(* Logix 5000 project; controller MNETR_V13 1756-L63 rev 13.1; software revision 13.03 *)

TASK MainTask (continuous, watchdog 500 ms) : MainProgram

MODULES
   Local : 1756-L63 (ICP 0, rev 13.1)
      LocalENBT : 1756-ENBT (ICP 3, Ethernet 105.102.0.224, rev 2.4)
         RemoteENBT : 1756-ENBT (Ethernet 105.102.0.210, rev 1.6, Output RPI 10 ms)
            MNETR : vendor 1 type 0 code 15 (ICP 1, rev 1.1, Output RPI 5 ms)
END_MODULES

TYPE MNETRBLOCKSTATS :
STRUCT
   Read : INT;   // Total number of read block transfers
   Write : INT;   // Total number of write block transfers
   Parse : INT;   // Total number of blocks parsed
   Event : INT;   // Total number of event blocks received
   Cmd : INT;   // Total number of command blocks received
   Err : INT;   // Total number of block transfer errors
END_STRUCT
END_TYPE

TYPE MNETRCLIENTSTATS :
STRUCT
   CmdReq : INT;   // Total number of command list requests sent
   CmdResp : INT;   // Total number of command list responses received
   CmdErr : INT;   // Total number of command list errors
   Requests : INT;   // Total number of requests for port
   Responses : INT;   // Total number of responses for port
   ErrSent : INT;   // Total number of errors sent
   ErrRec : INT;   // Total number of errors received
   CfgErrWord : INT;   // Configuration Error Word
   CurErr : INT;   // Current Error code
   LastErr : INT;   // Last recorded error code
END_STRUCT
END_TYPE

TYPE MNETRCMDCONTROL :
STRUCT
   CmdIndex : INT[6];   // Stores the command indexes for command control.
   NumberOfCommands : INT;   // Number of commands per block (1 to 6)
   CommandsAddedtoQueue : INT;   // Number of commands added to queue
   CmdControlTrigger : BOOL;   // Trigger Command Control. User application will activate this trigger.
END_STRUCT
END_TYPE

TYPE MNETRCOILARRAY :   // Conversion to INT values
STRUCT
   Boolean : BOOL[416];   // Conversion from Bool to INT data types
END_STRUCT
END_TYPE

TYPE MNETRCONTROL :   // Module Behaviour Control Tags. Values used by program for data transfer operation between the module and the processor.
STRUCT
   BootTimer : TIMER;   // Starts counting when user issues a coldboot or warmboot
   WarmBoot : BOOL;   // Causes software reset. The Module reads new configuration information.
   ColdBoot : BOOL;   // Causes hardware reset.
   EventCmdTrigger : BOOL;   // Trigger events to be executed by the module
   EventCmd : MNETREVENTCMD;   // Event command Data
   CmdControl : MNETRCMDCONTROL;   // Command control data
   PassThru : MNETRPASSTHRU;   // Pass thru data format
   IPAddress : MNETRIPADDRESS;   // Getting and Setting IP address to and from Module
END_STRUCT
END_TYPE

TYPE MNETRDATA :
STRUCT
   ReadData : INT[600];   // Data read from module
   WriteData : INT[600];   // Data to write to module
END_STRUCT
END_TYPE

TYPE MNETREVENTCMD :   // Data structure to use for Event message generation.
STRUCT
   IP0 : INT;   // First digit of IP address
   IP1 : INT;   // Second digit of IP address
   IP2 : INT;   // Third digit of IP address
   IP3 : INT;   // Last digit of IP address
   ServPort : INT;   // TCP Service Port number (0-65535), 502 for MBAP, 2000 for MNET
   Node : INT;   // Modbus slave node address (0 to 247)
   DBAddress : INT;   // Module internal database to use with message
   Count : INT;   // Register or data point count
   Swap : INT;   // Swap code to use with functions 3 and 4
   Function : INT;   // Modbus function code for message
   Address : INT;   // Address to interface with in device
   Result : INT;   // shows the result of the event that was sent
END_STRUCT
END_TYPE

TYPE MNETRIPADDRESS :   // Data structure to get and set the IP address of the module.
STRUCT
   IPGetTrigger : BOOL;   // Gets IP address.
   IPReceived : INT[4];   // IP address received.
   IPSetTrigger : BOOL;   // Sets IP address
   IPRequested : INT[4];   // IP address set.
END_STRUCT
END_TYPE

TYPE MNETRMODULEDEF :   // this defines the whole module which includes all tags used in the program
STRUCT
   DATA : MNETRDATA;   // Data read from module
   STATUS : MNETRSTATUS;   // Client ,Server Status and blocks status
   CONTROL : MNETRCONTROL;   // Module control warmboot, coldboot, etc
   UTIL : MNETRUTIL;   // command, event control
END_STRUCT
END_TYPE

TYPE MNETRPASSTHRU :   // Applicable with the selection of a Pass-Through mode (1 to 3) in the Configuration file.
STRUCT
   MBControl1 : CONTROL;   // Modbus pass thru message control
   MBControl2 : CONTROL;   // Modbus pass thru message control
   MBMsg : SINT[500];   // message array
   MBScratch : INT[3];   // temporary used ints
   MBOffsetBit : INT;   // offset bit in the message
   MBOffset : INT;   // start offset in the message
   MBMsgLen : INT;   // message length
   mbdouble : DINT;   // Modbus double int tag
   MBCoil : MNETRCOILARRAY;   // Conversion array
END_STRUCT
END_TYPE

TYPE MNETRSTATUS :
STRUCT
   PassCnt : INT;   // Program cycle counter
   ProductVersion : INT;   // Shows the module software version
   ProductCode : INT[2];   // This identifies the module product code
   BlockStats : MNETRBLOCKSTATS;   // Block Transfer Statistics.
   Reserved1 : INT;   // Reserved INT
   Reserved2 : INT;   // Reserved INT
   MNetReq : INT;   // number of remote client requests for port 502
   MNetResp : INT;   // number of server responses for port 502
   MBAPReq : INT;   // number of remote client requests for port 2000
   MBAPResp : INT;   // number of server responses for port 2000
   ClientStatus : MNETRCLIENTSTATS;   // Client Status
END_STRUCT
END_TYPE

TYPE MNETRUTIL :   // Variables for internal ladder usage - should not be accessed by user application
STRUCT
   LastRead : INT;   // Index of last read block
   LastWrite : INT;   // Index of last write block
   BlockIndex : INT;   // Computed block offset for data table
   ReadDataSizeGet : INT;   // Gets ReadData Array Length.
   WriteDataSizeGet : INT;   // Gets WriteData Array Length.
   ReadDataBlkCount : INT;   // Holds the value of the Block Counts of the Read Data Array. Array Size is divided by 40.
   WriteDataBlkCount : INT;   // Holds the value of the Block Counts of the Write Data Array. Array Size is divided by 40.
   RBTSremainder : INT;   // Holds remainder calculation value from the read array.
   WBTSremainder : INT;   // Holds remainder calculation value from the write array.
   IPsetPending : BOOL;   // Allows Setting module IP address
   IPgetPending : BOOL;   // Allows Getting module IP address
   InitOutBlkIDLim : INT;   // Block Index Limit for ReadData size of the array
END_STRUCT
END_TYPE

VAR_GLOBAL   (* controller tags *)
   MJFAULTS : DINT[12] := ([0] := 1272054862, [1] := 191551, [3] := 1256603824, [4] := 191551);
   MNETR : MNETRMODULEDEF;
END_VAR

PROGRAM MainProgram   (* routine attr 65 MainRoutine *)

ROUTINE MainRoutine   (* ladder *)
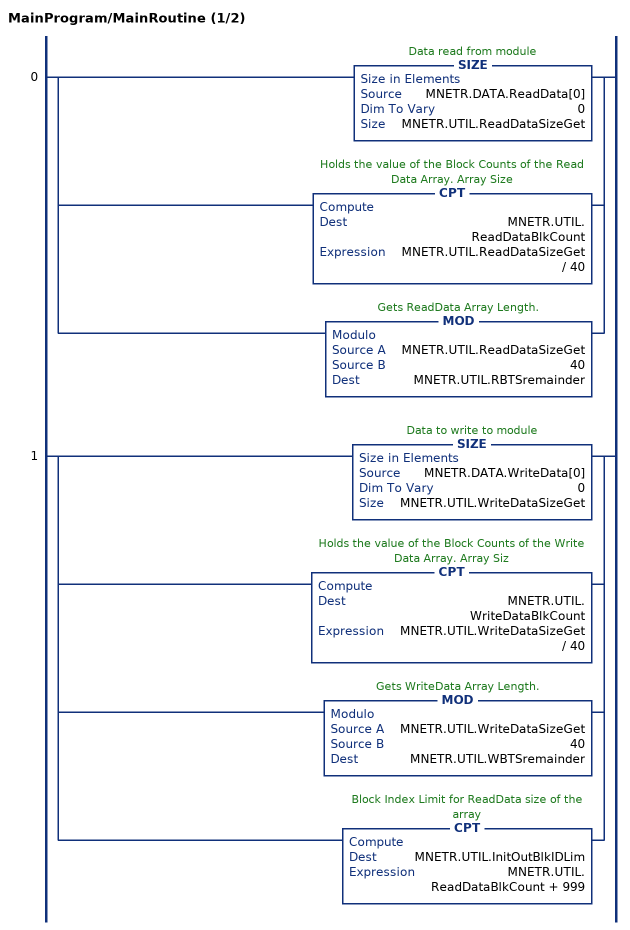
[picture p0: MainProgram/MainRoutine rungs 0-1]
   0: [SIZE(MNETR.DATA.ReadData[0],0,MNETR.UTIL.ReadDataSizeGet) ,CPT(MNETR.UTIL.ReadDataBlkCount,MNETR.UTIL.ReadDataSizeGet / 40) ,MOD(MNETR.UTIL.ReadDataSizeGet,40,MNETR.UTIL.RBTSremainder) ];
   1: [SIZE(MNETR.DATA.WriteData[0],0,MNETR.UTIL.WriteDataSizeGet) ,CPT(MNETR.UTIL.WriteDataBlkCount,MNETR.UTIL.WriteDataSizeGet / 40) ,MOD(MNETR.UTIL.WriteDataSizeGet,40,MNETR.UTIL.WBTSremainder) ,CPT(MNETR.UTIL.InitOutBlkIDLim,MNETR.UTIL.ReadDataBlkCount + 999) ];
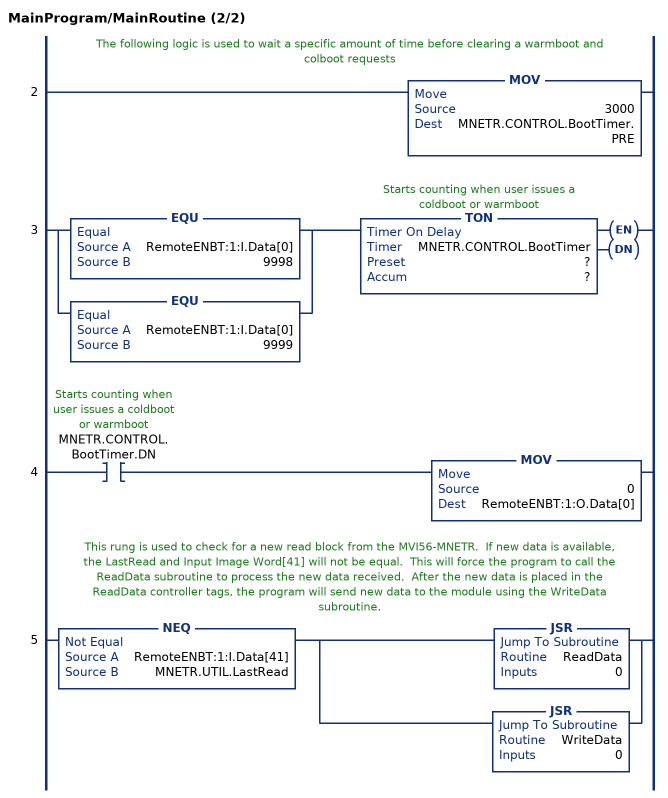
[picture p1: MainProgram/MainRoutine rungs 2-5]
   // The following logic is used to wait a specific amount of time before clearing a warmboot and colboot requests
   2: MOV(3000,MNETR.CONTROL.BootTimer.PRE);
   3: [EQU(RemoteENBT:1:I.Data[0],9998) ,EQU(RemoteENBT:1:I.Data[0],9999) ]TON(MNETR.CONTROL.BootTimer,?,?);
   4: XIC(MNETR.CONTROL.BootTimer.DN)MOV(0,RemoteENBT:1:O.Data[0]);
   // This rung is used to check for a new read block from the MVI56-MNETR.  If new data is available, the LastRead and Input Image Word[41] will not be equal.  This will force the program to call the ReadData subroutine to process the new data received.  After the new data is placed in the ReadData controller tags, the program will send new data to the module using the WriteData subroutine.
   5: NEQ(RemoteENBT:1:I.Data[41],MNETR.UTIL.LastRead)[JSR(ReadData,0) ,JSR(WriteData,0) ];
END_ROUTINE

ROUTINE ReadData   (* ladder *)
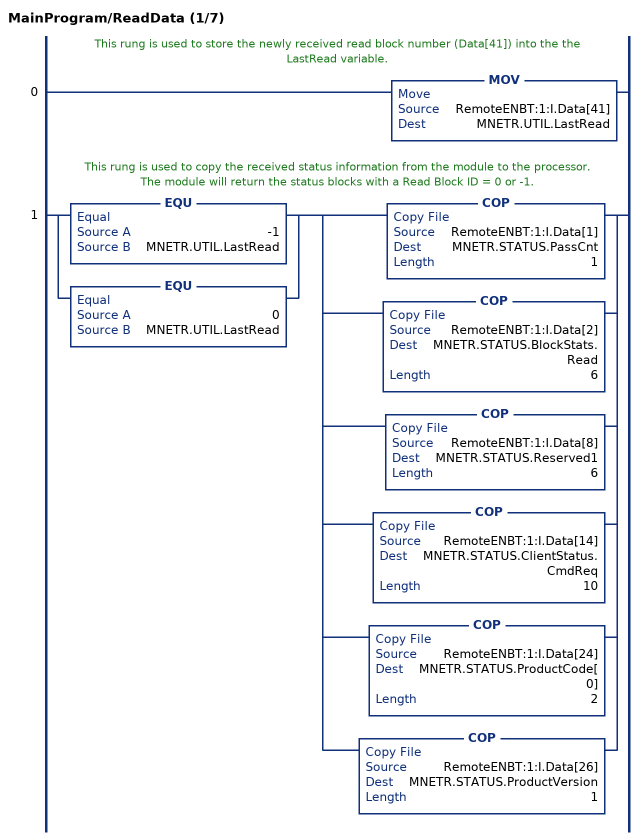
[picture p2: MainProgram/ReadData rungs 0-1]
   // This rung is used to store the newly received read block number (Data[41]) into the the LastRead variable.
   0: MOV(RemoteENBT:1:I.Data[41],MNETR.UTIL.LastRead);
   // This rung is used to copy the received status information from the module to the processor. The module will return the status blocks with a Read Block ID = 0 or -1.
   1: [EQU(-1,MNETR.UTIL.LastRead) ,EQU(0,MNETR.UTIL.LastRead) ][COP(RemoteENBT:1:I.Data[1],MNETR.STATUS.PassCnt,1) ,COP(RemoteENBT:1:I.Data[2],MNETR.STATUS.BlockStats.Read,6) ,COP(RemoteENBT:1:I.Data[8],MNETR.STATUS.Reserved1,6) ,COP(RemoteENBT:1:I.Data[14],MNETR.STATUS.ClientStatus.CmdReq,10) ,COP(RemoteENBT:1:I.Data[24],MNETR.STATUS.ProductCode[0],2) ,COP(RemoteENBT:1:I.Data[26],MNETR.STATUS.ProductVersion,1) ];
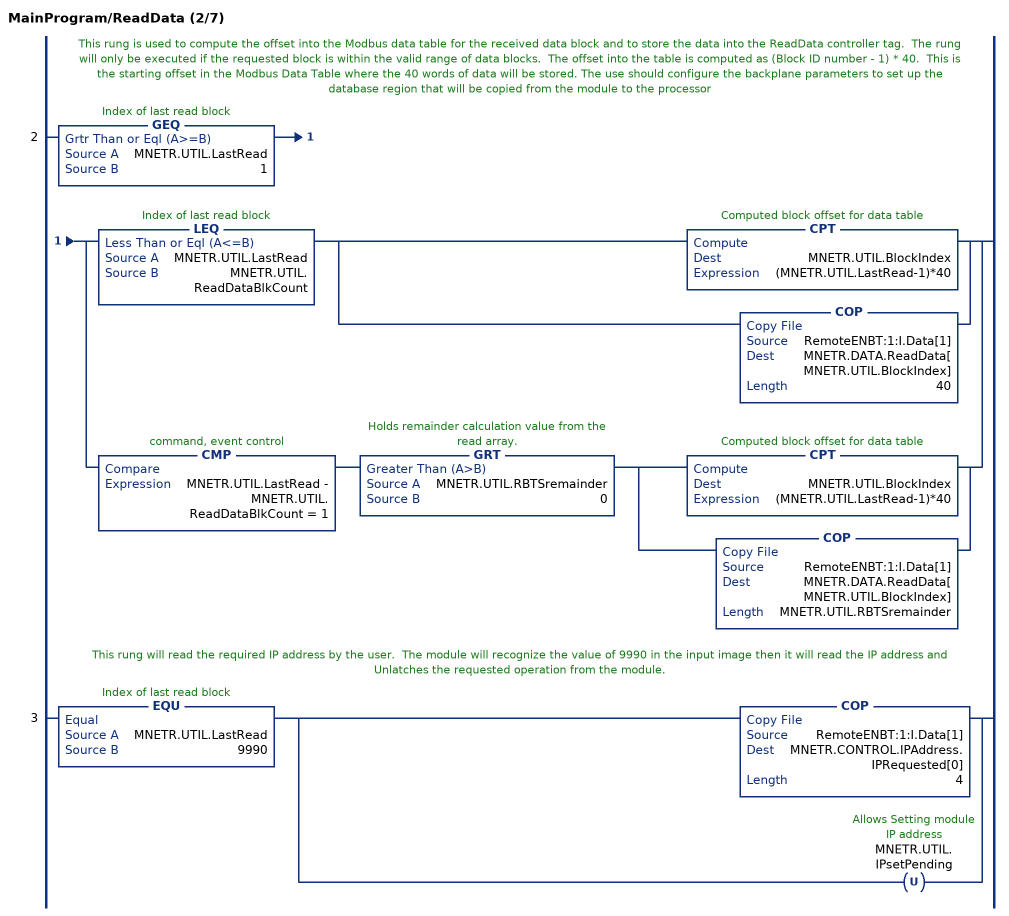
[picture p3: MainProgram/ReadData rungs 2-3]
   // This rung is used to compute the offset into the Modbus data table for the received data block and to store the data into the ReadData controller tag.  The rung will only be executed if the requested block is within the valid range of data blocks.  The offset into the table is computed as (Block ID number - 1) * 40.  This is the starting offset in the Modbus Data Table where the 40 words of data will be stored. The use should configure the backplane parameters to set up the database region that will be copied from the module to the processor
   2: GEQ(MNETR.UTIL.LastRead,1)[LEQ(MNETR.UTIL.LastRead,MNETR.UTIL.ReadDataBlkCount) [CPT(MNETR.UTIL.BlockIndex,(MNETR.UTIL.LastRead-1)*40) ,COP(RemoteENBT:1:I.Data[1],MNETR.DATA.ReadData[MNETR.UTIL.BlockIndex],40) ] ,CMP(MNETR.UTIL.LastRead - MNETR.UTIL.ReadDataBlkCount = 1) GRT(MNETR.UTIL.RBTSremainder,0) [CPT(MNETR.UTIL.BlockIndex,(MNETR.UTIL.LastRead-1)*40) ,COP(RemoteENBT:1:I.Data[1],MNETR.DATA.ReadData[MNETR.UTIL.BlockIndex],MNETR.UTIL.RBTSremainder) ] ];
   // This rung will read the required IP address by the user.  The module will recognize the value of 9990 in the input image then it will read the IP address and Unlatches the requested operation from the module.
   3: EQU(MNETR.UTIL.LastRead,9990)[COP(RemoteENBT:1:I.Data[1],MNETR.CONTROL.IPAddress.IPRequested[0],4) ,OTU(MNETR.UTIL.IPsetPending) ];
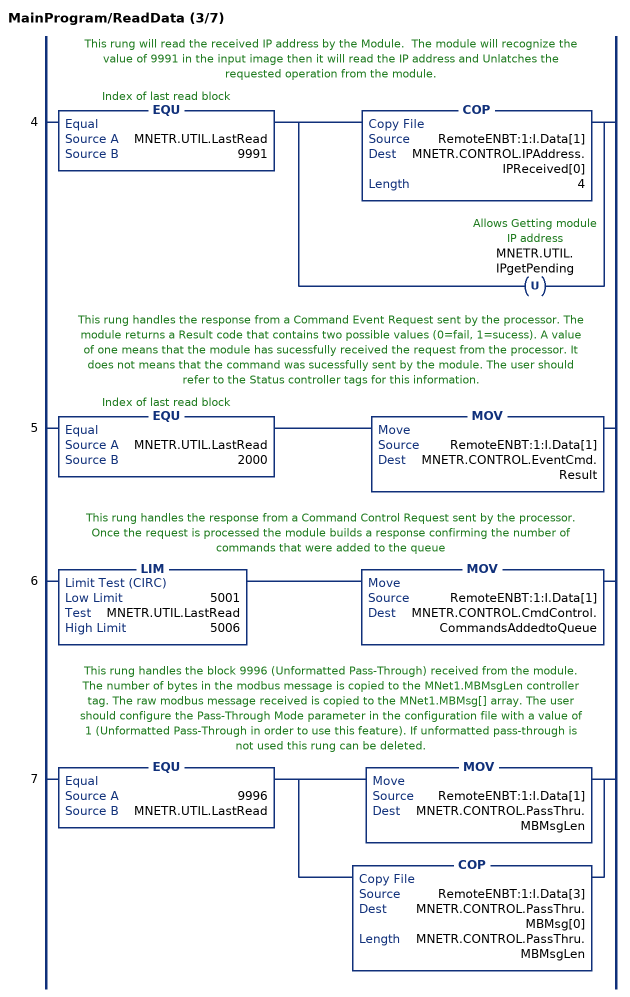
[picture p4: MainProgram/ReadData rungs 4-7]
   // This rung will read the received IP address by the Module.  The module will recognize the value of 9991 in the input image then it will read the IP address and Unlatches the requested operation from the module.
   4: EQU(MNETR.UTIL.LastRead,9991)[COP(RemoteENBT:1:I.Data[1],MNETR.CONTROL.IPAddress.IPReceived[0],4) ,OTU(MNETR.UTIL.IPgetPending) ];
   // This rung handles the response from a Command Event Request sent by the processor. The module returns a Result code that contains two possible values (0=fail, 1=sucess). A value of one means that the module has sucessfully received the request from the processor. It does not means that the command was sucessfully sent by the module. The user should refer to the Status controller tags for this information.
   5: EQU(MNETR.UTIL.LastRead,2000)MOV(RemoteENBT:1:I.Data[1],MNETR.CONTROL.EventCmd.Result);
   // This rung handles the response from a Command Control Request sent by the processor. Once the request is processed the module builds a response confirming the number of commands that were added to the queue
   6: LIM(5001,MNETR.UTIL.LastRead,5006)MOV(RemoteENBT:1:I.Data[1],MNETR.CONTROL.CmdControl.CommandsAddedtoQueue);
   // This rung handles the block 9996 (Unformatted Pass-Through) received from the module. The number of bytes in the modbus message is copied to the MNet1.MBMsgLen controller tag. The raw modbus message received is copied to the MNet1.MBMsg[] array. The user should configure the Pass-Through Mode parameter in the configuration file with a value of 1 (Unformatted Pass-Through in order to use this feature). If unformatted pass-through is not used this rung can be deleted.
   7: EQU(9996,MNETR.UTIL.LastRead)[MOV(RemoteENBT:1:I.Data[1],MNETR.CONTROL.PassThru.MBMsgLen) ,COP(RemoteENBT:1:I.Data[3],MNETR.CONTROL.PassThru.MBMsg[0],MNETR.CONTROL.PassThru.MBMsgLen) ];
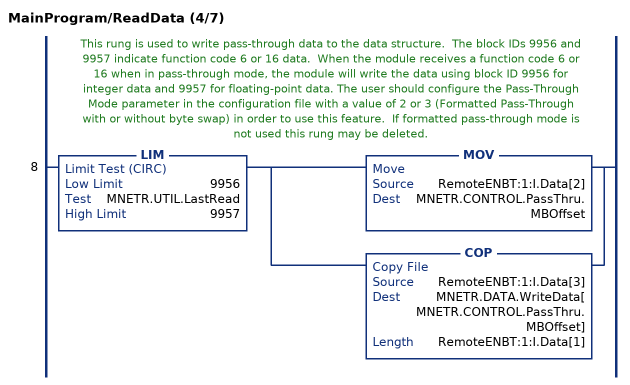
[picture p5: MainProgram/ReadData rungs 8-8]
   // This rung is used to write pass-through data to the data structure.  The block IDs 9956 and 9957 indicate function code 6 or 16 data.  When the module receives a function code 6 or 16 when in pass-through mode, the module will write the data using block ID 9956 for integer data and 9957 for floating-point data. The user should configure the Pass-Through Mode parameter in the configuration file with a value of 2 or 3 (Formatted Pass-Through with or without byte swap) in order to use this feature.  If formatted pass-through mode is not used this rung may be deleted.
   8: LIM(9956,MNETR.UTIL.LastRead,9957)[MOV(RemoteENBT:1:I.Data[2],MNETR.CONTROL.PassThru.MBOffset) ,COP(RemoteENBT:1:I.Data[3],MNETR.DATA.WriteData[MNETR.CONTROL.PassThru.MBOffset],RemoteENBT:1:I.Data[1]) ];
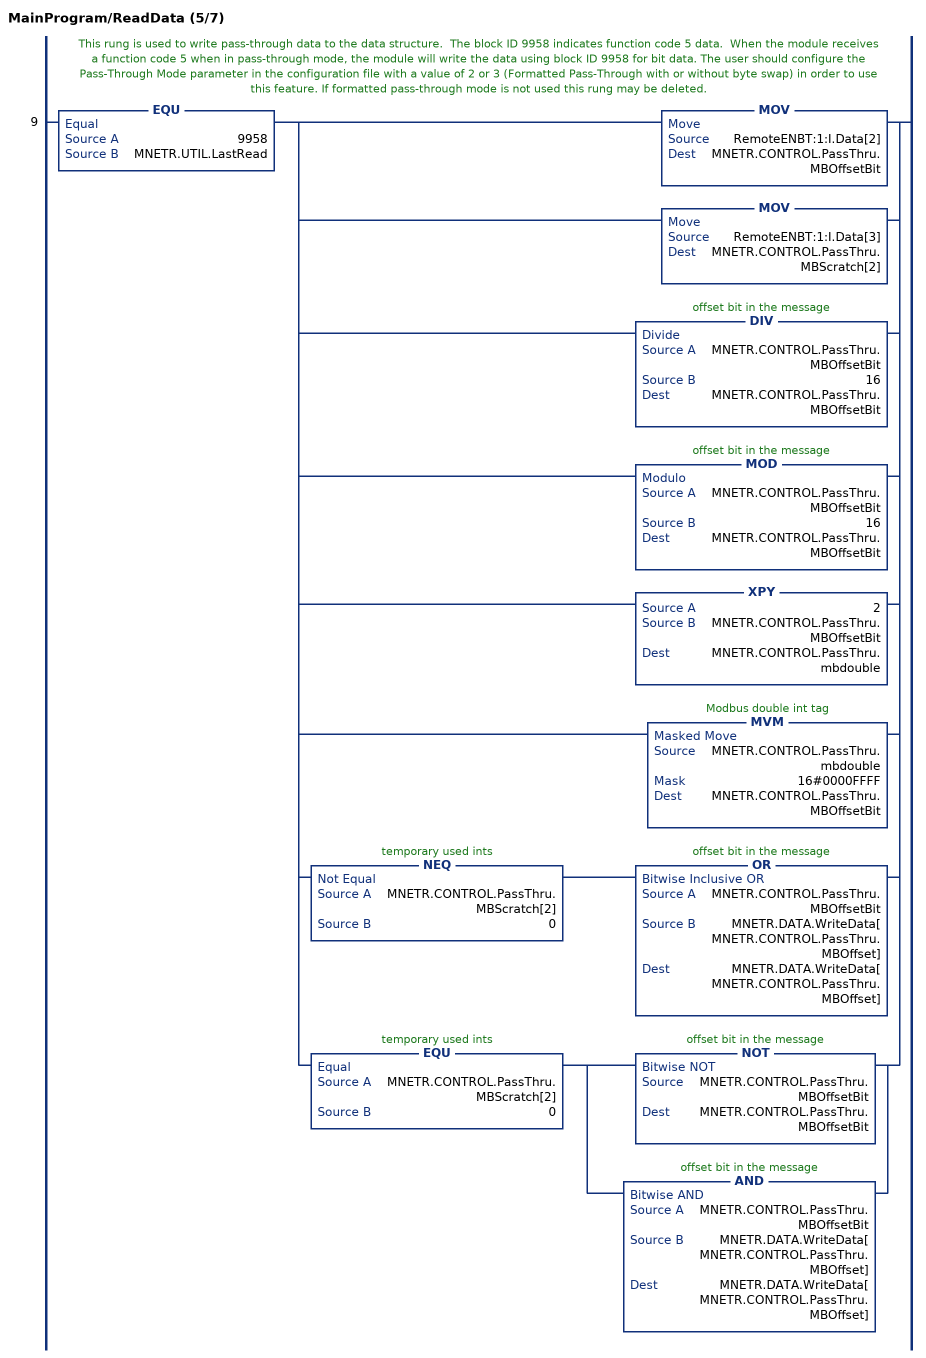
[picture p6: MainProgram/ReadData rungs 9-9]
   // This rung is used to write pass-through data to the data structure.  The block ID 9958 indicates function code 5 data.  When the module receives a function code 5 when in pass-through mode, the module will write the data using block ID 9958 for bit data. The user should configure the Pass-Through Mode parameter in the configuration file with a value of 2 or 3 (Formatted Pass-Through with or without byte swap) in order to use this feature. If formatted pass-through mode is not used this rung may be deleted.
   9: EQU(9958,MNETR.UTIL.LastRead)[MOV(RemoteENBT:1:I.Data[2],MNETR.CONTROL.PassThru.MBOffsetBit) ,MOV(RemoteENBT:1:I.Data[3],MNETR.CONTROL.PassThru.MBScratch[2]) ,DIV(MNETR.CONTROL.PassThru.MBOffsetBit,16,MNETR.CONTROL.PassThru.MBOffsetBit) ,MOD(MNETR.CONTROL.PassThru.MBOffsetBit,16,MNETR.CONTROL.PassThru.MBOffsetBit) ,XPY(2,MNETR.CONTROL.PassThru.MBOffsetBit,MNETR.CONTROL.PassThru.mbdouble) ,MVM(MNETR.CONTROL.PassThru.mbdouble,16#0000FFFF,MNETR.CONTROL.PassThru.MBOffsetBit) ,NEQ(MNETR.CONTROL.PassThru.MBScratch[2],0) OR(MNETR.CONTROL.PassThru.MBOffsetBit,MNETR.DATA.WriteData[MNETR.CONTROL.PassThru.MBOffset],MNETR.DATA.WriteData[MNETR.CONTROL.PassThru.MBOffset]) ,EQU(MNETR.CONTROL.PassThru.MBScratch[2],0) [NOT(MNETR.CONTROL.PassThru.MBOffsetBit,MNETR.CONTROL.PassThru.MBOffsetBit) ,AND(MNETR.CONTROL.PassThru.MBOffsetBit,MNETR.DATA.WriteData[MNETR.CONTROL.PassThru.MBOffset],MNETR.DATA.WriteData[MNETR.CONTROL.PassThru.MBOffset]) ] ];
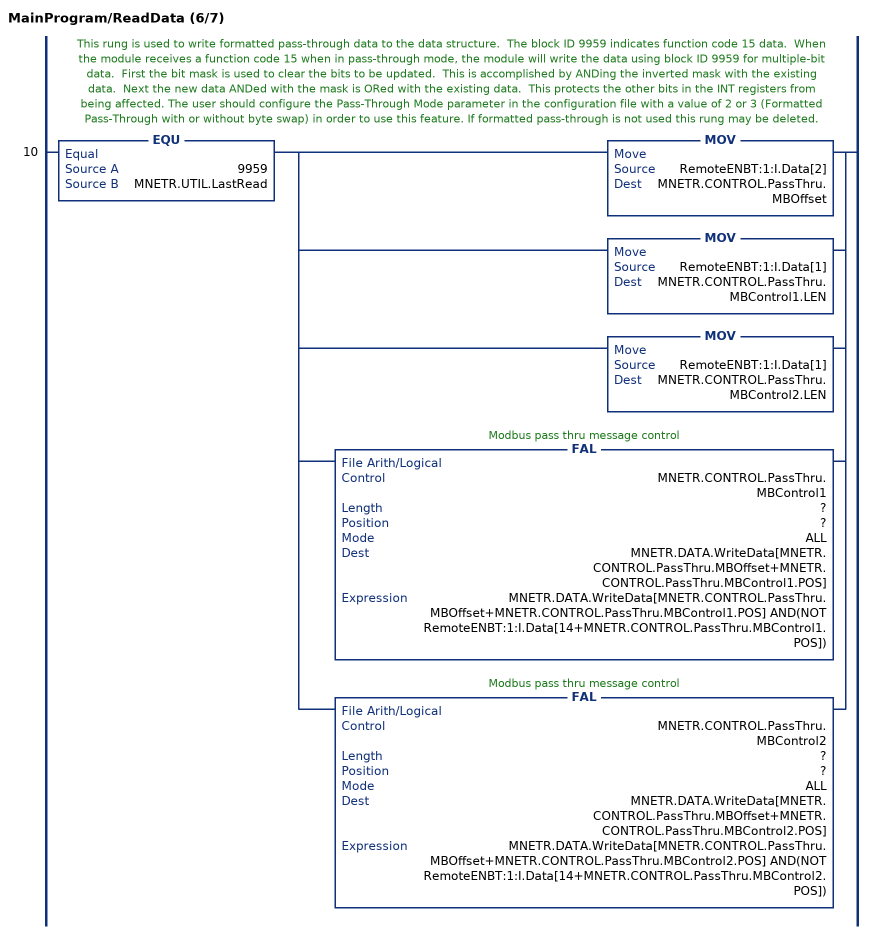
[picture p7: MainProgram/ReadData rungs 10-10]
   // This rung is used to write formatted pass-through data to the data structure.  The block ID 9959 indicates function code 15 data.  When the module receives a function code 15 when in pass-through mode, the module will write the data using block ID 9959 for multiple-bit data.  First the bit mask is used to clear the bits to be updated.  This is accomplished by ANDing the inverted mask with the existing data.  Next the new data ANDed with the mask is ORed with the existing data.  This protects the other bits in the INT registers from being affected. The user should configure the Pass-Through Mode parameter in the configuration file with a value of 2 or 3 (Formatted Pass-Through with or without byte swap) in order to use this feature. If formatted pass-through is not used this rung may be deleted.
   10: EQU(9959,MNETR.UTIL.LastRead)[MOV(RemoteENBT:1:I.Data[2],MNETR.CONTROL.PassThru.MBOffset) ,MOV(RemoteENBT:1:I.Data[1],MNETR.CONTROL.PassThru.MBControl1.LEN) ,MOV(RemoteENBT:1:I.Data[1],MNETR.CONTROL.PassThru.MBControl2.LEN) ,FAL(MNETR.CONTROL.PassThru.MBControl1,?,?,ALL,MNETR.DATA.WriteData[MNETR.CONTROL.PassThru.MBOffset+MNETR.CONTROL.PassThru.MBControl1.POS],MNETR.DATA.WriteData[MNETR.CONTROL.PassThru.MBOffset+MNETR.CONTROL.PassThru.MBControl1.POS] AND(NOT RemoteENBT:1:I.Data[14+MNETR.CONTROL.PassThru.MBControl1.POS])) ,FAL(MNETR.CONTROL.PassThru.MBControl2,?,?,ALL,MNETR.DATA.WriteData[MNETR.CONTROL.PassThru.MBOffset+MNETR.CONTROL.PassThru.MBControl2.POS],MNETR.DATA.WriteData[MNETR.CONTROL.PassThru.MBOffset+MNETR.CONTROL.PassThru.MBControl2.POS] AND(NOT RemoteENBT:1:I.Data[14+MNETR.CONTROL.PassThru.MBControl2.POS])) ];
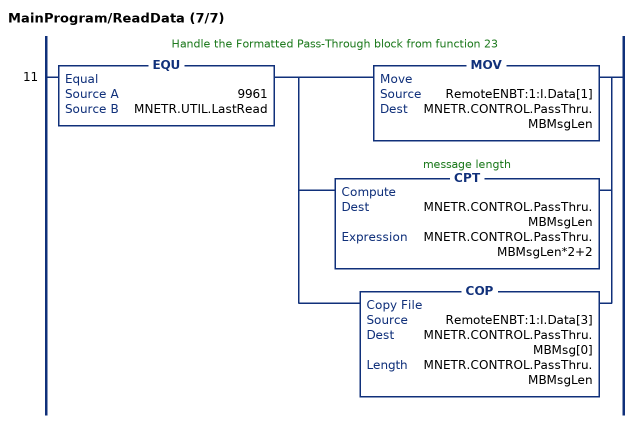
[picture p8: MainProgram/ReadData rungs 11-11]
   // Handle the Formatted Pass-Through block from function 23
   11: EQU(9961,MNETR.UTIL.LastRead)[MOV(RemoteENBT:1:I.Data[1],MNETR.CONTROL.PassThru.MBMsgLen) ,CPT(MNETR.CONTROL.PassThru.MBMsgLen,MNETR.CONTROL.PassThru.MBMsgLen*2+2) ,COP(RemoteENBT:1:I.Data[3],MNETR.CONTROL.PassThru.MBMsg[0],MNETR.CONTROL.PassThru.MBMsgLen) ];
END_ROUTINE

ROUTINE WriteData   (* ladder *)
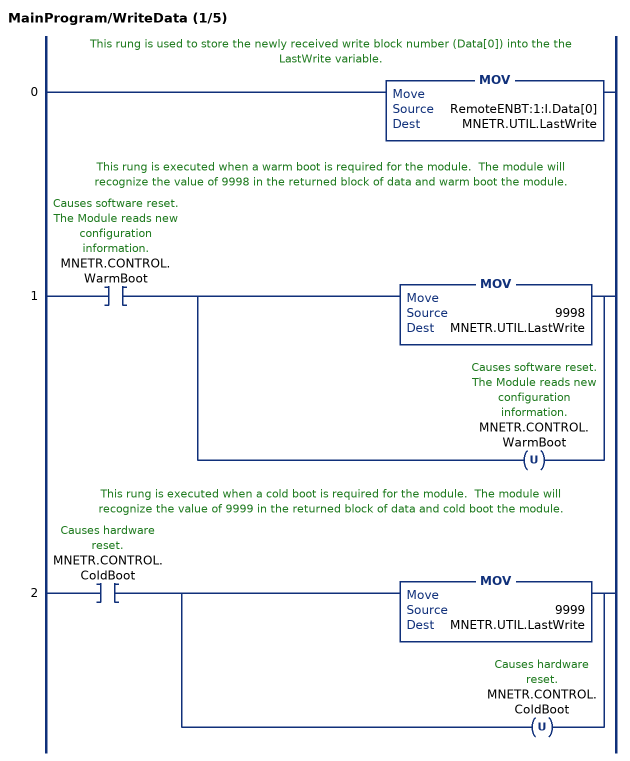
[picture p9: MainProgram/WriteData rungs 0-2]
   // This rung is used to store the newly received write block number (Data[0]) into the the LastWrite variable.
   0: MOV(RemoteENBT:1:I.Data[0],MNETR.UTIL.LastWrite);
   // This rung is executed when a warm boot is required for the module.  The module will recognize the value of 9998 in the returned block of data and warm boot the module.
   1: XIC(MNETR.CONTROL.WarmBoot)[MOV(9998,MNETR.UTIL.LastWrite) ,OTU(MNETR.CONTROL.WarmBoot) ];
   // This rung is executed when a cold boot is required for the module.  The module will recognize the value of 9999 in the returned block of data and cold boot the module.
   2: XIC(MNETR.CONTROL.ColdBoot)[MOV(9999,MNETR.UTIL.LastWrite) ,OTU(MNETR.CONTROL.ColdBoot) ];
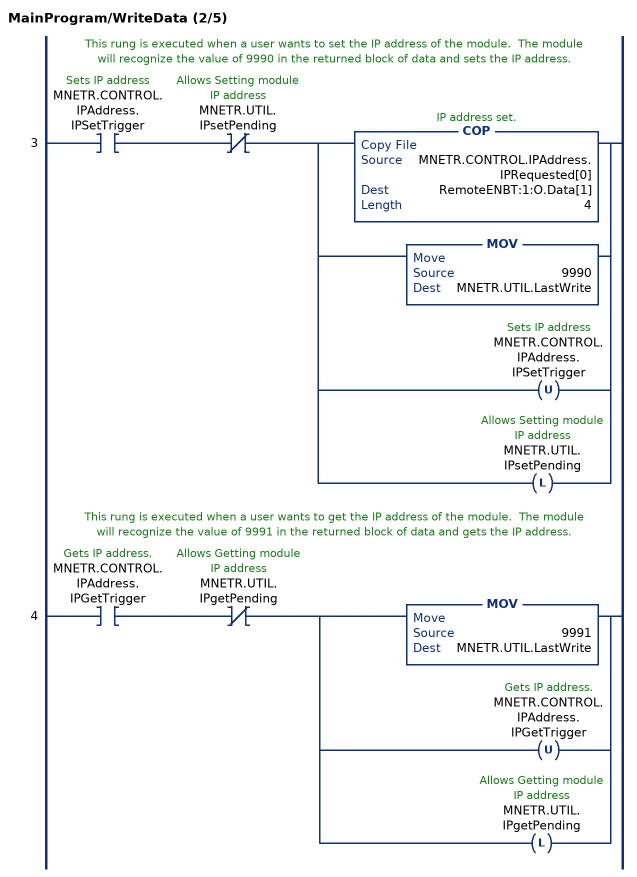
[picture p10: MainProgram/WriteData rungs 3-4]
   // This rung is executed when a user wants to set the IP address of the module.  The module will recognize the value of 9990 in the returned block of data and sets the IP address.
   3: XIC(MNETR.CONTROL.IPAddress.IPSetTrigger)XIO(MNETR.UTIL.IPsetPending)[COP(MNETR.CONTROL.IPAddress.IPRequested[0],RemoteENBT:1:O.Data[1],4) ,MOV(9990,MNETR.UTIL.LastWrite) ,OTU(MNETR.CONTROL.IPAddress.IPSetTrigger) ,OTL(MNETR.UTIL.IPsetPending) ];
   // This rung is executed when a user wants to get the IP address of the module.  The module will recognize the value of 9991 in the returned block of data and gets the IP address.
   4: XIC(MNETR.CONTROL.IPAddress.IPGetTrigger)XIO(MNETR.UTIL.IPgetPending)[MOV(9991,MNETR.UTIL.LastWrite) ,OTU(MNETR.CONTROL.IPAddress.IPGetTrigger) ,OTL(MNETR.UTIL.IPgetPending) ];
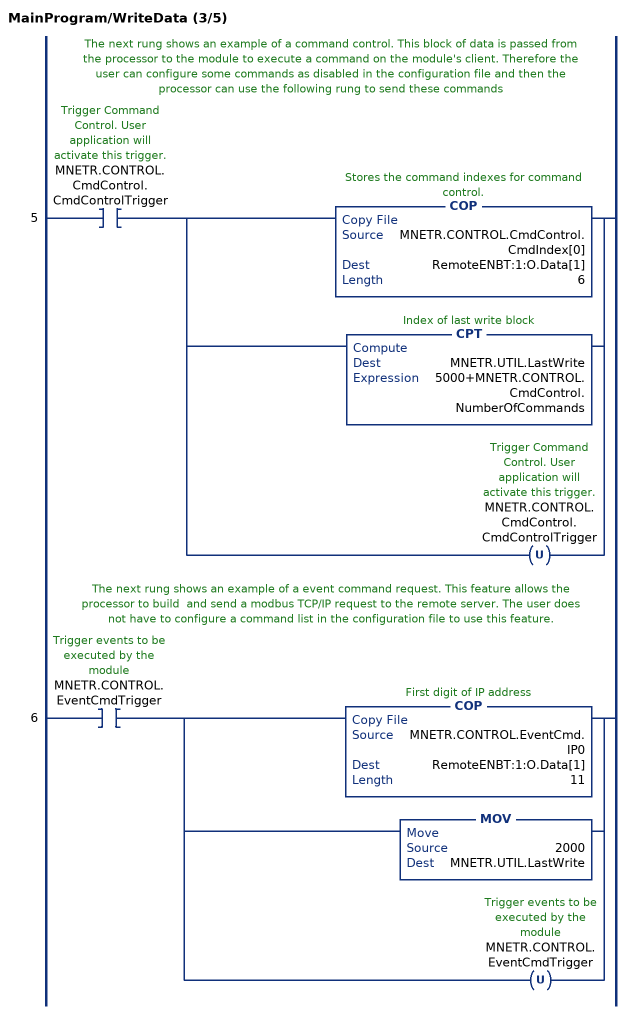
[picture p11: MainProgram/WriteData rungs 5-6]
   // The next rung shows an example of a command control. This block of data is passed from the processor to the module to execute a command on the module's client. Therefore the user can configure some commands as disabled in the configuration file and then the processor can use the following rung to send these commands
   5: XIC(MNETR.CONTROL.CmdControl.CmdControlTrigger)[COP(MNETR.CONTROL.CmdControl.CmdIndex[0],RemoteENBT:1:O.Data[1],6) ,CPT(MNETR.UTIL.LastWrite,5000+MNETR.CONTROL.CmdControl.NumberOfCommands) ,OTU(MNETR.CONTROL.CmdControl.CmdControlTrigger) ];
   // The next rung shows an example of a event command request. This feature allows the processor to build  and send a modbus TCP/IP request to the remote server. The user does not have to configure a command list in the configuration file to use this feature.
   6: XIC(MNETR.CONTROL.EventCmdTrigger)[COP(MNETR.CONTROL.EventCmd.IP0,RemoteENBT:1:O.Data[1],11) ,MOV(2000,MNETR.UTIL.LastWrite) ,OTU(MNETR.CONTROL.EventCmdTrigger) ];
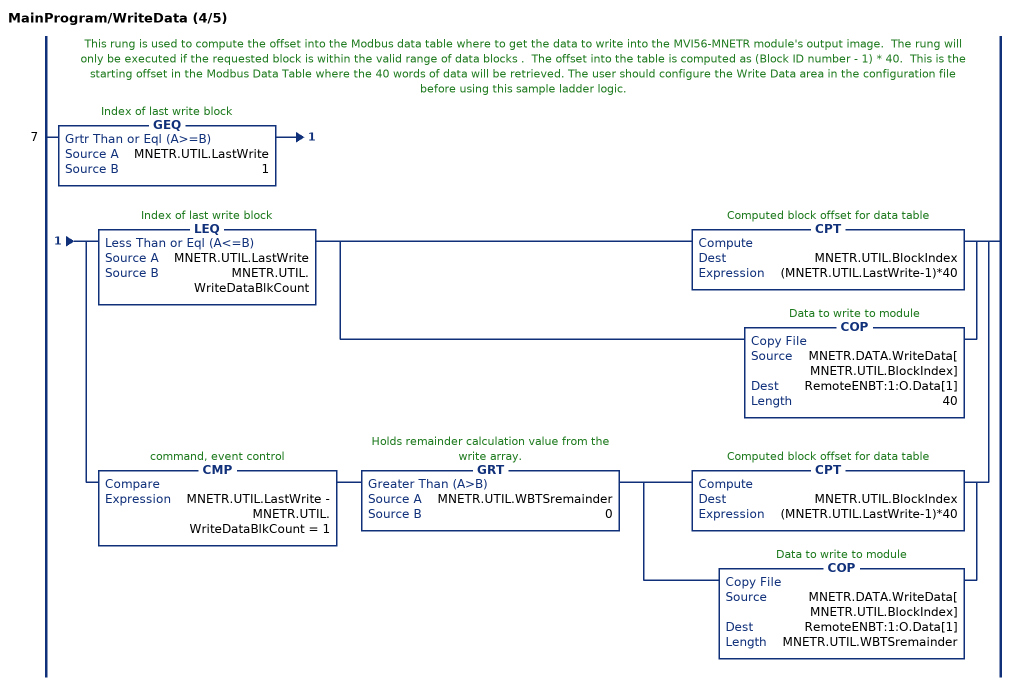
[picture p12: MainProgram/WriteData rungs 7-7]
   // This rung is used to compute the offset into the Modbus data table where to get the data to write into the MVI56-MNETR module's output image.  The rung will only be executed if the requested block is within the valid range of data blocks .  The offset into the table is computed as (Block ID number - 1) * 40.  This is the starting offset in the Modbus Data Table where the 40 words of data will be retrieved. The user should configure the Write Data area in the configuration file before using this sample ladder logic.
   7: GEQ(MNETR.UTIL.LastWrite,1)[LEQ(MNETR.UTIL.LastWrite,MNETR.UTIL.WriteDataBlkCount) [CPT(MNETR.UTIL.BlockIndex,(MNETR.UTIL.LastWrite-1)*40) ,COP(MNETR.DATA.WriteData[MNETR.UTIL.BlockIndex],RemoteENBT:1:O.Data[1],40) ] ,CMP(MNETR.UTIL.LastWrite - MNETR.UTIL.WriteDataBlkCount = 1) GRT(MNETR.UTIL.WBTSremainder,0) [CPT(MNETR.UTIL.BlockIndex,(MNETR.UTIL.LastWrite-1)*40) ,COP(MNETR.DATA.WriteData[MNETR.UTIL.BlockIndex],RemoteENBT:1:O.Data[1],MNETR.UTIL.WBTSremainder) ] ];
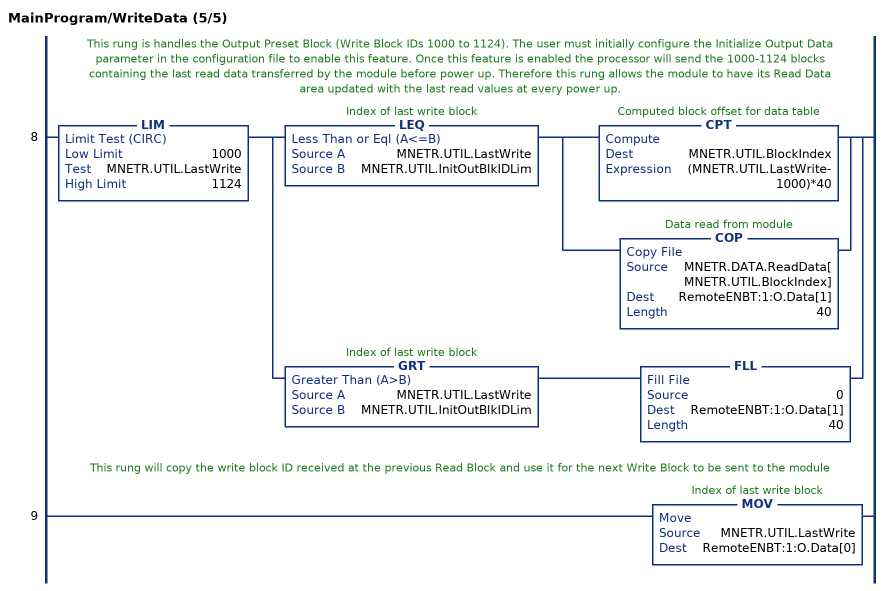
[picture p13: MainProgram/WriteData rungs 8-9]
   // This rung is handles the Output Preset Block (Write Block IDs 1000 to 1124). The user must initially configure the Initialize Output Data parameter in the configuration file to enable this feature. Once this feature is enabled the processor will send the 1000-1124 blocks containing the last read data transferred by the module before power up. Therefore this rung allows the module to have its Read Data area updated with the last read values at every power up.
   8: LIM(1000,MNETR.UTIL.LastWrite,1124)[LEQ(MNETR.UTIL.LastWrite,MNETR.UTIL.InitOutBlkIDLim) [CPT(MNETR.UTIL.BlockIndex,(MNETR.UTIL.LastWrite-1000)*40) ,COP(MNETR.DATA.ReadData[MNETR.UTIL.BlockIndex],RemoteENBT:1:O.Data[1],40) ] ,GRT(MNETR.UTIL.LastWrite,MNETR.UTIL.InitOutBlkIDLim) FLL(0,RemoteENBT:1:O.Data[1],40) ];
   // This rung will copy the write block ID received at the previous Read Block and use it for the next Write Block to be sent to the module
   9: MOV(MNETR.UTIL.LastWrite,RemoteENBT:1:O.Data[0]);
END_ROUTINE
END_PROGRAM

PROGRAM StartUp   (* routine attr 65 PowerUp *)

ROUTINE PowerUp   (* ladder *)
// This routine is executed each time the module is powered up or restarted.
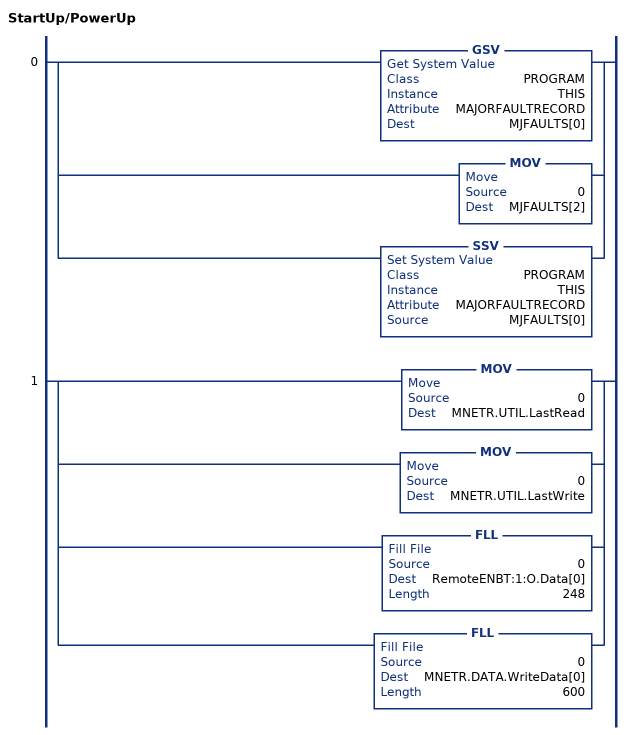
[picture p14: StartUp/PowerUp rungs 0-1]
   0: [GSV(PROGRAM,THIS,MAJORFAULTRECORD,MJFAULTS[0]) ,MOV(0,MJFAULTS[2]) ,SSV(PROGRAM,THIS,MAJORFAULTRECORD,MJFAULTS[0]) ];
   1: [MOV(0,MNETR.UTIL.LastRead) ,MOV(0,MNETR.UTIL.LastWrite) ,FLL(0,RemoteENBT:1:O.Data[0],248) ,FLL(0,MNETR.DATA.WriteData[0],600) ];
END_ROUTINE
END_PROGRAM
